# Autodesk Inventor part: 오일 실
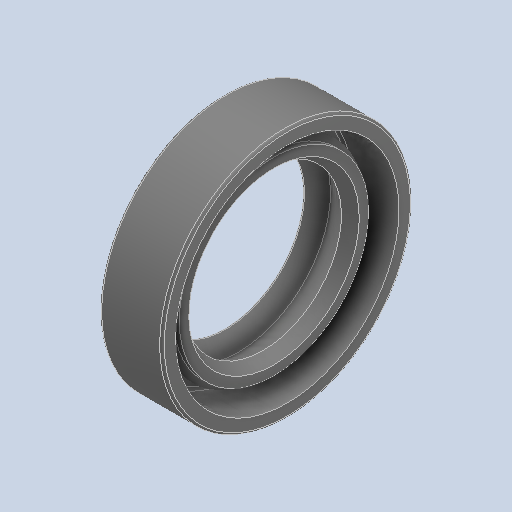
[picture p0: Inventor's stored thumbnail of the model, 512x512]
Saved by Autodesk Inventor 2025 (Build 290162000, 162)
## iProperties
Created: 2024-08
Part Number: 오일 실
Material: 고무
Description: 오일-실
Document SubType Name: Modeling
Designer: samsung
Density: 0.93 g/cm^3
Appearance: 기본값
Author: jhkim
Sending System: Autodesk Inventor 2025
Preprocessor: ST-DEVELOPER v20
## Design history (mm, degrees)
feature "Solid1"
node "솔리드1"
